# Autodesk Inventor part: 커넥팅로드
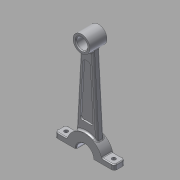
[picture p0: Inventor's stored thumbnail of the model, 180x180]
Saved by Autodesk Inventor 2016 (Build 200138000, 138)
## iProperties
Created: 2016-11
Part Number: 커넥팅로드
Material: 알루미늄 6061
Document SubType Name: Modeling
Designer: mduedu
Density: 2.71 g/cm^3
Mass: 62.0577 g
Surface Area: 108.143 cm^2
Volume: 22.8995 cm^3
Appearance: 알루미늄 - 평지
Author: mduedu
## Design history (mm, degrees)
sketch "스케치1" dims "d0" = 42, "d3" = 20
  geometry: L1 (0, 0)-(0, 114); L2 (-7.5, 107.386)-(-12.5, 16.875); L3 (7.5, 107.386)-(12.5, 16.875); C1 r 10 at (0, 0); C2 r 6.5 at (0, 114); 3 further points
  constraints: 6 end point, 4 coincident, 2 centre point, 2 symmetric about line, 1 vertical, 6 other
  dimensions: "d1" = 20 diameter of C1; "d2" = 13 diameter of C2; "d4" = 114 distance of L1.start L1.end; "d6" = 12.5 distance from line of L1 L2.end; "d7" = 7.5 distance from line of L1 L2.start
extrude "돌출1" new body sketch "스케치1" stored distance "d8" = 13; taper "d9" = 0 deg
extrude "돌출2" join sketch "스케치1" stored distance "d10" = 20; taper "d11" = 0 deg
sketch "스케치2"
  geometry: L1 (-7.5, 107.386)-(-12.5, 16.875) reference; L2 (7.5, 107.386)-(12.5, 16.875) reference; A1 r 10 centre (0, 114) between (-7.5, 107.386) and (7.5, 107.386) reference; A2 r 21 centre (0, 0) between (-12.5, 16.875) and (12.5, 16.875) reference; 1 further point
extrude "돌출3" join sketch "스케치2" stored distance "d12" = 8; taper "d13" = 0 deg
sketch "스케치3"
  geometry: L1 (-7.5, 107.386)-(-12.5, 16.875) reference; L2 (7.5, 107.386)-(12.5, 16.875) reference; L3 (-4.209, 94.448)-(-7.768, 30.011); L4 (4.209, 94.448)-(7.768, 30.011); L5 (0, 94)-(0, 31); A1 r 10 centre (0, 114) between (-7.5, 107.386) and (7.5, 107.386) reference; A2 r 21 centre (0, 0) between (-12.5, 16.875) and (12.5, 16.875) reference; A3 r 20 centre (0, 114) between (-4.209, 94.448) and (4.209, 94.448); A4 r 31 centre (0, 0) between (7.768, 30.011) and (-7.768, 30.011); 1 further point
  constraints: 6 end point, 6 point on circle, 2 centre point, 2 parallel, 1 symmetric about line, 1 vertical alignment
  dimensions: "d18" = 10 radial gap between concentric circles of A3 A1; "d19" = 10 radial gap between concentric circles of A2 A4; "d20" = 4 distance between parallel lines of L3 L1
extrude "돌출4" cut sketch "스케치3" distance "d21" = 2; taper "d22" = 0 deg
fillet "모깎기1" dims "d23" = 3
fillet "모깎기2" dims "d24" = 2
fillet "모깎기3" dims "d25" = 2
chamfer "모따기1" distance "d26" = 1; stored, may be unused: second distance "d27" = 2, angle "d28" = 45 deg
sketch "스케치4"
  geometry: L1 (-35, -6)-(-20.125, -6); L2 (35, -6)-(35, 6); L3 (35, 6)-(20.125, 6); L4 (-35, 6)-(-35, -6); L5 (-35, -6)-(35, 6); L6 (35, -6)-(-35, 6); L7 (-20.125, 6)-(-35, 6); L8 (20.125, 6)-(-20.125, 6); L9 (20.125, -6)-(35, -6); L10 (-20.125, -6)-(20.125, -6); A1 r 21 centre (0, 0) between (-20.125, 6) and (20.125, 6) reference; 1 further point
  constraints: 20 end point, 10 parallel, 4 point on circle, 3 horizontal, 3 perpendicular, 2 midpoint
  dimensions: "d29" = 70 distance of L1.start L2.start; "d31" = 12 distance of L2.start L2.end
extrude "돌출5" join sketch "스케치4" stored distance "d32" = 0; taper "d33" = 0 deg
fillet "모깎기4" dims "d34" = 3
fillet "모깎기5" dims "d35" = 1
fillet "모깎기6" dims "d36" = 1
sketch "스케치5"
  geometry: L1 (1, 0)-(1, 7) reference; L2 (-24, 13.5)-(-44, 13.5) reference; L3 (-44, -6.5)-(-24, -6.5) reference; L4 (-34, 13.5)-(-34, -6.5); 3 further points
  constraints: 2 end point, 2 midpoint, 1 horizontal alignment, 1 symmetric about line
  dimensions: "d37" = 7 distance from line of point (-6, 3.5) L1
feature "분할1"
sketch "스케치6"
  geometry: 2 further points
  constraints: 2 other
hole "구멍1" sketch "스케치6" at (-62, 3.5), (-6, 3.5) diameter "d38" = 4.5; stored, may be unused: countersink angle "d42" = 90 deg, drill point angle "d44" = 0 deg; dims "d39" = 6, "d40" = 4, "d41" = 2, "d43" = 8
node "솔리드1"
mirror "대칭1"
other parameters: "d16" = 4, "d17" = 4
